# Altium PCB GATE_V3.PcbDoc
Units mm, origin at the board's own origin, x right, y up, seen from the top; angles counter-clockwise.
Board outline 71.37 x 50.42 mm, 2 copper layers (Top Layer, Bottom Layer); 47 components, 44 nets, 244 pads, 54 vias.
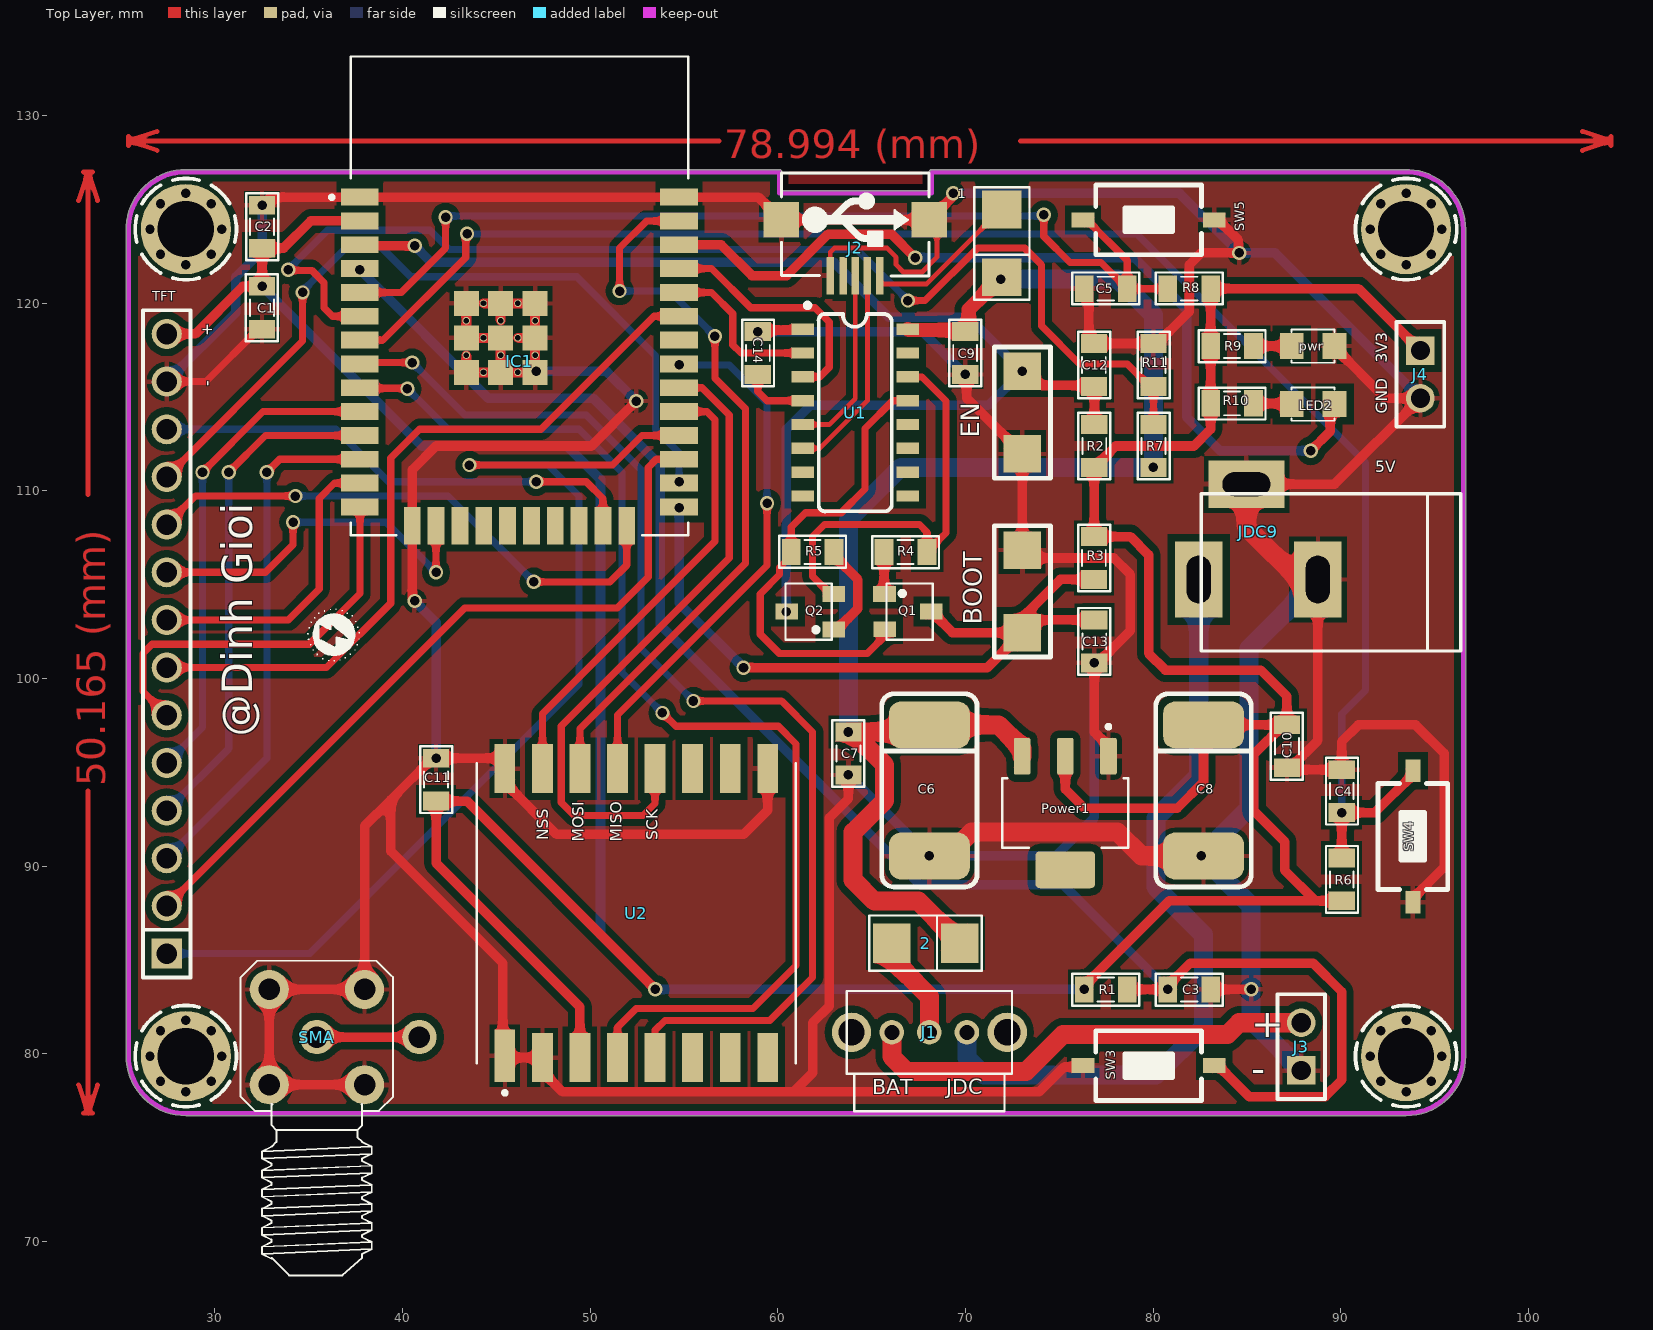
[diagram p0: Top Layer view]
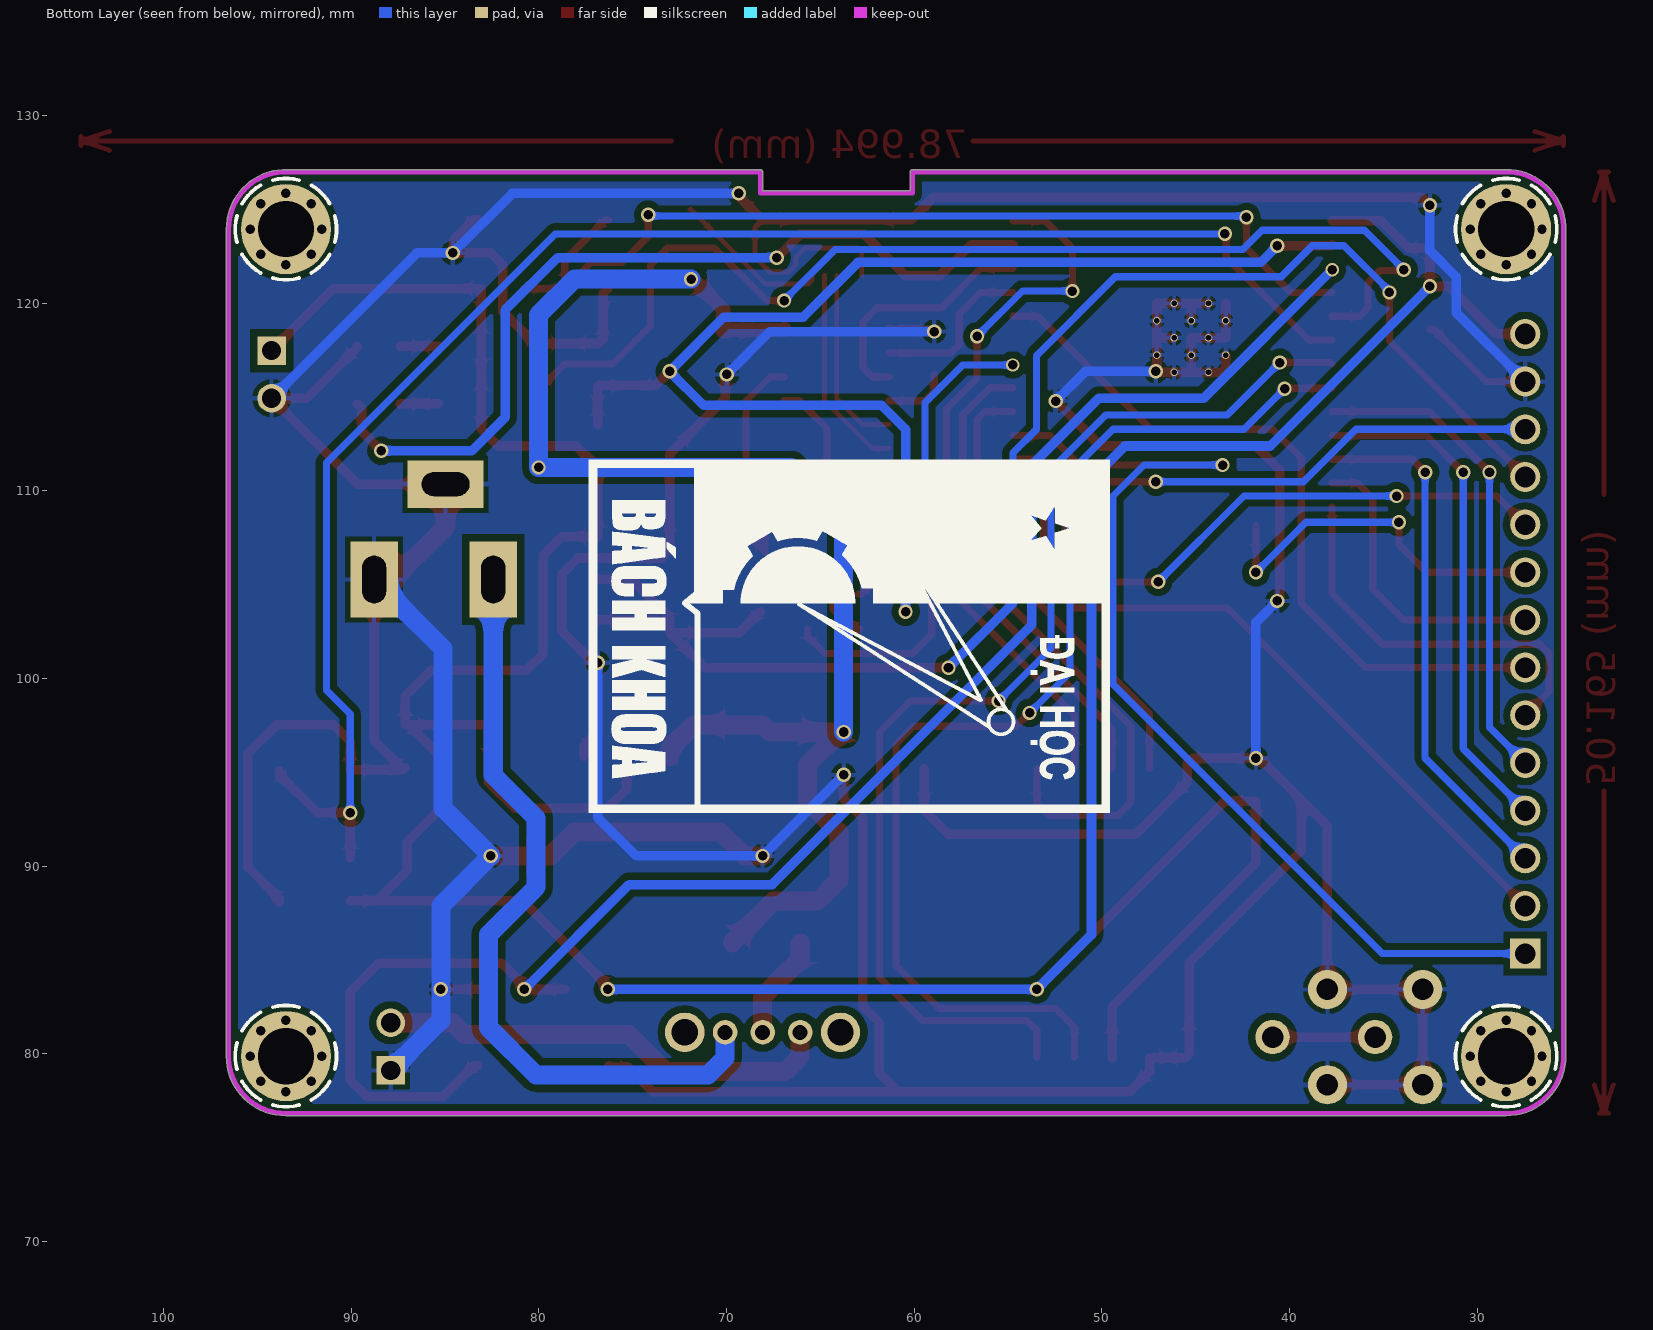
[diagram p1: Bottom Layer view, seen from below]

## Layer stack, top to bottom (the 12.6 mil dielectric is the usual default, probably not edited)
Top Solder: solder mask 0.0102, Solder Resist, Dk 3.5
Top Layer: signal copper 0.0356
Dielectric 1: dielectric 0.32, FR-4, Dk 4.8
Bottom Layer: signal copper 0.0356
Bottom Solder: solder mask 0.0102, Solder Resist, Dk 3.5

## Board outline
28.447,76.708 cw(c28.448,79.883) 25.273,79.883 25.273,123.825 cw(c25.4,123.825) 25.274,123.846 cw(c28.448,123.952) 28.448,127.127 cw(c28.448,127) 28.449,127.127 60.071,127.127 cw(c60.071,127) 60.198,127 60.198,125.984 68.072,125.984 68.072,127 cw(c68.199,127) 68.199,127.127 93.599,127.127 cw(c93.599,127) 93.631,127.123 cw(c93.472,123.952) 96.647,123.952 cw(c96.52,123.952) 96.647,123.951 96.647,80.01 cw(c96.52,80.01) 96.646,79.989 cw(c93.472,79.883) 96.647,79.883 cw(c93.472,79.883) 93.472,76.708 28.448,76.708 cw(c28.448,76.835)

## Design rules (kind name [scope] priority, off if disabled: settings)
Clearance [All] p1: gap=0.254 ignorepadtopadclearanceinfootprint=TRUE except(0.381: Arc-Fill Arc-Poly Arc-Region Track-Fill Track-Poly Track-Region SMDPad-Fill SMDPad-Poly SMDPad-Region THPad-Fill THPad-Poly THPad-Region Via-Fill Via-Poly Via-Region Fill-Fill Fill-Poly Fill-Region Poly-Poly Poly-Region Region-Region)
PolygonConnect [All] p1: connectstyle=Relief reliefconductorwidth=0.254 reliefentries=4 polygonreliefangle="90 Angle" airgapwidth=0.254
RoutingVias [All] p1: holewidth=0.508 width=0.762 viastyle="Through Hole" minholewidth=0.508 minwidth=0.762 maxholewidth=0.711 maxwidth=1.27
SolderMaskExpansion [All] p1: expansion=0.102
Width [All] p1: maxlimit=1.016 minlimit=0.254 preferedwidth=0.508
30 further rules are at their usual default settings.

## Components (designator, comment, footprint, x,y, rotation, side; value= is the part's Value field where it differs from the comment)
1 "S4" DIO-214AC(SMA) 71.882,123.116 r90 top
2 "S4" DIO-214AC(SMA) 67.945,85.852 r180 top
BOOT "SW" "SW 3x2x4" 73.025,104.648 r90 top value="SW chip 2 pin" (schematic designator SW2)
C1 "10uF" CAP_0805 32.512,119.761 r270 top value=33p
C2 "100nF" CAP_0805 32.512,124.079 r90 top value=33p
C3 "100nF" CAP_0805 81.915,83.439 r0 top value=33p
C4 "100nF" CAP_0805 90.043,94.001 r90 top value=33p
C5 "100nF" CAP_0805 77.47,120.777 r180 top value=33p
C6 "22uF/10V" CAP_7343 68.072,94.107 r270 top
C7 "100nF" CAP_0805 63.754,96.012 r270 top value=33p
C8 "22uF/10V" CAP_7343 82.677,94.107 r270 top
C9 "10uF" CAP_0805 69.977,117.348 r90 top value=33p
C10 "100nF" CAP_0805 87.122,96.393 r270 top value=33p
C11 "10uF" CAP_0805 41.783,94.615 r90 top value=33p
C12 "100nF" CAP_0805 76.835,116.713 r90 top value=33p
C13 "100nF" CAP_0805 76.86,101.981 r270 top value=33p
C14 "100nF" CAP_0805 58.928,117.348 r90 top value=33p
EN "SW" "SW 3x2x4" 73.025,114.173 r270 top value="SW chip 2 pin" (schematic designator SW1)
IC1 "ESP32-WROOM-32" MODULE_ESP32-WROOM-32 46.228,120.396 r0 top
J1 "SK12D07VG4" SK12D07VG4 68.07,81.153 r0 top
J2 "USB-5" USB-M1 64.12,121.476 r0 top
J3 "JP2" JP2-C1T 87.884,79.121 r90 top
J4 "JP2" JP2-C1T 94.234,117.475 r270 top
JDC9 "Jac DC" DC-IN 85.598,107.823 r180 top
LED2 "LED" LED-0805-Blue 87.376,114.631 r0 top value="LED 3 ly Single Colour"
Power1 "AMS1117-3V3" SOT230P700X180-4N 75.311,92.837 r270 top
pwr "LED" LED-0805-Blue 87.376,117.717 r0 top value="LED 3 ly Single Colour" (schematic designator LED1)
Q1 "2SC1815" SOT23D 66.929,103.569 r270 top value=C1815
Q2 "2SC1815" SOT23D 61.722,103.569 r90 top value=C1815
R1 "10k" RES_SMD_0805 77.47,83.439 r0 top
R2 "10k" RES-SMD-0805 76.86,112.395 r270 top
R3 "10k" RES-SMD-0805 76.835,106.426 r90 top
R4 "10k" RES-SMD-0805 66.802,106.744 r0 top
R5 "10k" RES-SMD-0805 61.849,106.744 r180 top
R6 "10k" RES_SMD_0805 90.043,89.302 r90 top
R7 "31k" RES-SMD-0805 80.01,112.395 r90 top
R8 "10k" RES_SMD_0805 81.915,120.777 r180 top
R9 "1k" RES-SMD-0805 84.201,117.717 r0 top
R10 "1k" RES-SMD-0805 84.201,114.669 r0 top
R11 "11k" RES-SMD-0805 80.01,116.713 r90 top
SMA "210111003" SMA-RA 35.433,80.899 r0 top
SW3 "SW" SW-SMD 79.756,79.375 r0 top value="SW chip 2 pin"
SW4 "SW" SW-SMD 93.832,91.588 r90 top value="SW chip 2 pin"
SW5 "SW" SW-SMD 79.756,124.444 r180 top value="SW chip 2 pin"
TFT "JP14" JP14-D1T 27.432,85.344 r90 top
U1 "CH340C" SOP-16 64.12,114.173 r270 top
U2 "Ra-02 LoRa" Ra-02 52.451,87.503 r90 top

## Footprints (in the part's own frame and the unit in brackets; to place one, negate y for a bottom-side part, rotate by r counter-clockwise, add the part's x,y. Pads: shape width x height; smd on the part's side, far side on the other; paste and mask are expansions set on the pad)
CAP_0805 [mil]
  rect 39.37x55 smd: 1(-45,0) 2(45,0)
  silkscreen extent -70,-34 70,33, body extent -40,-25 40,25, height 24
CAP_7343 [mm] "Capacitor Tantalum 7343"
  rrect50% 2.5x4.3 smd: 1(-3.429,0) 2(3.556,0)
  silkscreen extent -5.08,-2.54 5.21,2.54, body extent -3.75,-2.14 3.75,2.16, height 2.8
DC-IN [mil] "Jac DC input"
  rect 100x160 hole 50 slot 100 at 90 deg: 1(125,100) 2(-125,100)
  rect 160x100 hole 50 slot 100 at 0 deg: 3(25,-100)
  silkscreen extent -425,-80 120,250, body extent -410,-105 134,269, height 434
DIO-214AC(SMA) [mm] "DO-214AC Diode Smallest Size"
  rect 2x2.1 smd: 1(1.88,-0.051) 2(-1.732,-0.051)
  silkscreen extent -2.92,-1.52 3.07,1.42, body extent -2.5,-1.35 2.7,1.25, height 2.4
JP2-C1T [mm] "2 row, straight, gold plating"
  rect 1.52x1.52 hole 1.02: 1(0,0)
  round 1.52 hole 1.02: 2(2.54,0)
  silkscreen extent -1.52,-1.27 4.06,1.27, body extent -1.52,-1.25 4.06,1.25, height 8.51
JP14-D1T [mm] "14 pins, 1 row, straight, gold plating"
  rect 1.6x1.6 hole 1.1: 1(0,0)
  round 1.6 hole 1.1: 2(2.54,0) 3(5.08,0) 4(7.62,0) 5(10.16,0) 6(12.7,0) 7(15.24,0) 8(17.78,0) 9(20.32,0) 10(22.86,0) 11(25.4,0) 12(27.94,0) 13(30.48,0) 14(33.02,0)
  silkscreen extent -1.27,-1.27 34.29,1.27, body extent -1.27,-1.27 34.29,1.27, height 8.54
LED-0805-Blue [mil]
  rect 50x55 smd: 1(0,0) 2(90,0)
  silkscreen extent 0,-35 90,35, body extent 5,-25 85,25, height 43
MODULE_ESP32-WROOM-32 [mm]
  rect 2x0.9 smd: 1(-8.5,5.26) 2(-8.5,3.99) 3(-8.5,2.72) 4(-8.5,1.45) 5(-8.5,0.18) 6(-8.5,-1.09) 7(-8.5,-2.36) 8(-8.5,-3.63) 9(-8.5,-4.9) 10(-8.5,-6.17) 11(-8.5,-7.44) 12(-8.5,-8.71) 13(-8.5,-9.98) 14(-8.5,-11.25) 25(8.5,-11.25) 26(8.5,-9.98) 27(8.5,-8.71) 28(8.5,-7.44) 29(8.5,-6.17) 30(8.5,-4.9) 31(8.5,-3.63) 32(8.5,-2.36) 33(8.5,-1.09) 34(8.5,0.18) 35(8.5,1.45) 36(8.5,2.72) 37(8.5,3.99) 38(8.5,5.26)
  rect 0.9x2 smd: 15(-5.715,-12.25) 16(-4.445,-12.25) 17(-3.175,-12.25) 18(-1.905,-12.25) 19(-0.635,-12.25) 20(0.635,-12.25) 21(1.905,-12.25) 22(3.175,-12.25) 23(4.445,-12.25) 24(5.715,-12.25)
  rect 1.33x1.33 smd: 39_1(-2.835,-0.405) 39_2(-1,-0.405) 39_3(0.835,-0.405) 39_4(-2.835,-2.24) 39_5(-1,-2.24) 39_6(0.835,-2.24) 39_7(-2.835,-4.075) 39_8(-1,-4.075) 39_9(0.835,-4.075)
  round 0.4 hole 0.3: 39_10(-1.917,-0.405) 39_11(-0.082,-0.405) 39_12(-2.835,-1.322) 39_13(-1,-1.322) 39_14(0.835,-1.322) 39_15(-1.917,-2.24) 39_16(-0.082,-2.24) 39_17(-2.835,-3.157) 39_18(-1,-3.157) 39_19(0.835,-3.157) 39_20(-1.917,-4.075) 39_21(-0.082,-4.075)
  silkscreen extent -10.1,-12.75 9,12.75, body extent -10.54,-12.75 8.98,12.75, height 3.2
Ra-02 [mm]
  rect 2.8x1.1 smd: 1(-7.6,7)
  rect 2.6x1.1 smd: 2(-7.7,5) 3(-7.7,3) 4(-7.7,1) 5(-7.7,-1) 6(-7.7,-3) 7(-7.7,-5) 8(-7.7,-7) 9(7.7,-7) 10(7.7,-5) 11(7.7,-3) 12(7.7,-1) 13(7.7,1) 14(7.7,3) 15(7.7,5) 16(7.7,7)
  silkscreen extent -9.68,-8.5 8,8.5, body extent -8,-8.49 8,8.51, height 3.03
RES-SMD-0805 [mil]
  rect 39.37x55 smd: 1(-45,0) 2(45,0)
  silkscreen extent -70,-34 70,33, body extent -39,-25 39,25, height 31
RES_SMD_0805 [mil]
  rect 39.37x55 smd: 1(-45,0) 2(45,0)
  silkscreen extent -70,-34 70,33, body extent -39,-25 39,25, height 31
SK12D07VG4 [mm]
  round 1.308 hole 0.8: 1(-2,0) 2(2,0) COM(0,0)
  round 2.1 hole 1.4: M1(-4.15,0) M2(4.15,0)
  silkscreen extent -4.4,-4.2 4.4,2.2
SMA-RA [mil]
  round 72 hole 45: 1(0,0)
  round 82 hole 45: 2(-100,-100) 3(100,-100) 4(100,100) 5(-100,100)
  silkscreen extent -160,-500 160,160, body extent -136,-457 139,137, height 394
SOP-16 [mm]
  rect 0.6x1.2 smd: 1(-4.445,-2.8) 2(-3.175,-2.8) 3(-1.905,-2.8) 4(-0.635,-2.8) 5(0.635,-2.8) 6(1.905,-2.8) 7(3.175,-2.8) 8(4.445,-2.8) 9(4.445,2.8) 10(3.175,2.8) 11(1.905,2.8) 12(0.635,2.8) 13(-0.635,2.8) 14(-1.905,2.8) 15(-3.175,2.8) 16(-4.445,2.8)
  silkscreen extent -5.84,-2.67 5.26,1.95, body extent -4.95,-3.47 4.95,3.47, height 1.75
SOT23D [mm] "SOT 23C - 1-3-2 - BCE"
  rect 0.85x1.2 smd: 1(-0.95,-1.25) 2(0.94,-1.245) 3(0,1.25)
  silkscreen extent -1.5,-1.14 1.5,1.32, body extent -1.5,-1.17 1.5,1.33, height 1.06
SOT230P700X180-4N [mm]
  rrect25% 1.97x0.89 smd: 1(-3.025,2.3) 2(-3.025,0) 3(-3.025,-2.3)
  rrect25% 1.97x3.19 smd: 4(3.025,0)
  silkscreen extent -4.7,-3.35 1.85,3.35
"SW 3x2x4" [mm]
  rect 2x2 smd: 1(-2.2,0) 2(2.2,0)
  silkscreen extent -3.5,-1.5 3.5,1.5, body extent -2.45,-1.45 2.45,1.45, height 2
SW-SMD [mm] "Switch SMD type"
  rect 1.2x0.8 smd: 1(-3.5,0) 2(3.5,0)
  silkscreen extent -2.82,-1.85 2.82,1.85, body extent -3.05,-1.85 3.05,1.85, height 2.5
USB-M1 [mm]
  rect 0.4x2 smd: 1(1.3,0) 2(0.65,0) 3(0,0) 4(-0.65,0) 5(-1.321,0)
  rect 1.9x1.9 smd: 5(-3.95,2.968) 5(3.95,2.968)
  silkscreen extent -3.94,-0.03 3.94,5.46, body extent -3.98,0.11 4,5.54, height 2.71

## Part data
1 2: library part "Diode S4", "D醤"
BOOT EN SW3 SW4 SW5: library part SW2, "Switch button 2 pin"
C1 C2 C3 C4 C5 C7 C9 C10 C11 C12 C13 C14: library part CapSMD, "Capacitor"
C6 C8: library part CAP_TAN_SMD, "Polazied Tantalum Capacitor"
IC1: "Bluetooth, WiFi Transceiver Module 2.4GHz ~ 2.5GHz Surface Mount", Package="Module Espressif Systems"
J1: "Switch Slide ON ON SPDT Side Slide 0.3A 30VDC PC Pins Bracket Mount/Through Hole Bulk", Package=None
J2: Manufacturer=FCI, Manufacturer Part Number=10118193-0001LF, Supplier Part Number 1=609-4616-1-ND
J3 J4: "WR-PHD 2.54 mm Angled Socket Header", Manufacturer="Würth Elektronik eiSos GmbH", partNo=613002143121
JDC9: library part DCIN, "Jac DC input"
LED2 pwr: "LED Single colour Green and Red"
Power1: library part LM1117, "800mA Low-Dropout Linear Regulator"
Q1 Q2: library part C1815, "NPN 600mW, ECB"
R1 R4 R5 R6 R8: library part "Resistor - SMD", "Resistor SMD", Manufacturer="Generic Components"
R2 R3 R7 R9 R10 R11: library part "Resistor - SMD", "Resistor", Manufacturer="Generic Components"
SMA: library part "CON Ant", "CONNECTOR ANTEN", Manufacturer="W黵th Elektronik eiSos GmbH"
TFT: "WR-PHD 2.54 mm Angled Socket Header", Manufacturer="Würth Elektronik eiSos GmbH", partNo=613014143121
U1: "USB to serial chip CH340", Package=Package
U2: "LoRa Module Ra-02"

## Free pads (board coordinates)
  round 4.8 hole 3: 16(28.448,79.883) 16(28.448,123.952) 16(93.472,79.883) 16(93.472,123.952)
  round 0.5 hole 0.5: 17(30.353,79.883) 17(30.353,123.952) 17(95.377,79.883) 17(95.377,123.952) 18(29.795,81.23) 18(29.795,125.299) 18(94.819,81.23) 18(94.819,125.299) 19(28.448,81.788) 19(28.448,125.857) 19(93.472,81.788) 19(93.472,125.857) 20(27.101,81.23) 20(27.101,125.299) 20(92.125,81.23) 20(92.125,125.299) 21(26.543,79.883) 21(26.543,123.952) 21(91.567,79.883) 21(91.567,123.952) 22(27.101,78.536) 22(27.101,122.605) 22(92.125,78.536) 22(92.125,122.605) 23(28.448,77.978) 23(28.448,122.047) 23(93.472,77.978) 23(93.472,122.047) 24(29.795,78.536) 24(29.795,122.605) 24(94.819,78.536) 24(94.819,122.605)
  round 1.829 hole 1.143: 25(40.894,80.899)

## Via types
v1: diameter 0.762, hole 0.508, Top Layer to Bottom Layer, 51 vias
v2: diameter 0.711, hole 0.508, Top Layer to Bottom Layer, 3 vias

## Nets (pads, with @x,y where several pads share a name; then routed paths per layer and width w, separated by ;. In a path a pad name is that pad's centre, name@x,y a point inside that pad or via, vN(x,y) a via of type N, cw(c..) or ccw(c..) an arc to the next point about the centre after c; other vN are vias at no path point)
3V3: C1.1 C2.1 C8.1 C10.1 C11.1 IC1.2 J4.1 Power1.2 R1.1 R2.2 R3.2 R6.1 R8.1 R9.1 R10.1 TFT.14 U2.3 | length 214.1
  Top Layer w0.508: TFT.14 28.956,118.364 31.496,120.904 v1(32.512,120.904) C2.1 33.655,122.936 35.105,124.386 IC1.2 ; U2.3 49.451,82.502 41.783,90.17 C11.1 43.434,93.472 v1(53.467,83.439) ; Power1.2 75.311,94.107 76.327,93.091 81.28,93.091 82.677,94.488 C8.1 C10.1@86.923,97.536 ; v1(76.327,83.439) 76.327,83.637 80.849,88.159 R6.1 ; 88.582,88.201 86.995,89.789 86.995,91.313 85.363,92.945 85.363,95.976 C10.1@86.923,97.536 ; J4.1 90.932,120.777 R8.1 R9.1 R10.1 83.058,113.284 82.169,112.395 78.003,112.395 R2.2 76.848,111.239 76.848,107.582 R3.2 78.781,107.569 79.756,106.594 79.756,101.346 80.645,100.457 85.725,100.457 87.122,99.06 C10.1 C10.1@86.924,97.536
  Bottom Layer w0.508: v1(32.512,120.904) 41.021,112.395 48.768,112.395 50.546,110.617 50.546,86.36 v1(53.467,83.439) v1(76.327,83.439)
5V: 1.2 2.2 C6.1 C7.1 C9.2 Power1.3 R7.1 U1.16 | length 79.6
  Top Layer w0.762: U1.16 66.966,118.572 69.896,118.572 C9.2 70.16,118.491 70.168,118.499 70.168,119.668 71.883,121.384 1.2
  Top Layer w1.016: v1(63.754,97.155) 63.937,97.155 65.684,95.407 65.684,93.497 64.008,91.821 64.008,89.266 65.136,88.138 67.492,88.138 69.677,85.953 2.2 ; C7.1@63.762,97.163 67.699,97.163 C6.1 71.751,97.536 73.011,96.276 Power1.3
  Bottom Layer w1.016: v1(63.754,97.155) 63.754,108.458 66.548,111.252 v1(80.01,111.252) 80.01,119.38 78.105,121.285 v1(71.882,121.285)
Adapter: J1.2 JDC9.1 | length 41.3
  Bottom Layer w1.016: J1.2 70.07,79.79 70.993,78.867 80.137,78.867 82.677,81.407 82.677,86.351 80.137,88.891 80.137,92.566 82.423,94.852 JDC9.1
ANTTEN: pad.25 SMA.1 | length 5.5
  Top Layer w0.508: SMA.1 pad.25
CH340_RX: IC1.35 U1.3 | length 13.2
  Top Layer w0.381: IC1.35 56.462,121.846 58.547,119.761 61.976,119.761 62.738,118.999 62.738,116.586 62.23,116.078 U1.3
CH340_TX: IC1.34 U1.2 | length 8.9
  Top Layer w0.381: IC1.34 56.462,120.576 57.594,119.444 57.594,117.78 58.027,117.348 U1.2
CS: IC1.23 TFT.12 | length 26.2
  Top Layer w0.381: v1(47.117,110.49) 49.784,110.49 50.673,109.601 IC1.23
  Bottom Layer w0.381: TFT.12 36.449,113.284 39.243,110.49 v1(47.117,110.49)
D+: J2.3 U1.5 | length 9.9
  Top Layer w0.254: U1.5 62.738,113.538 64.12,114.92 J2.3
D-: J2.2 U1.6 | length 11.2
  Top Layer w0.254: U1.6 62.23,112.268 64.77,114.808 J2.2
D/C: IC1.24 TFT.10 | length 29.5
  Top Layer w0.381: TFT.10 28.956,109.728 v1(34.29,109.728) ; v1(46.99,105.156) 51.054,105.156 51.943,106.045 IC1.24
  Bottom Layer w0.381: v1(34.29,109.728) 42.418,109.728 v1(46.99,105.156)
EN: C12.1 EN.1 IC1.3 Q2.3 R2.1 | length 67.9
  Top Layer w0.508: IC1.3 37.781,123.063 v1(40.64,123.063) ; v1(60.452,103.569) Q2.3 ; v1(73.025,116.373) 73.771,115.627 76.778,115.627 C12.1 76.86,115.545 R2.1
  Bottom Layer w0.508: v1(40.64,123.063) 41.529,122.174 62.992,122.174 65.913,119.253 70.145,119.253 v1(73.025,116.373) 71.206,114.554 61.722,114.554 60.452,113.284 v1(60.452,103.569)
feedback: IC1.6 R7.2 R11.1 | length 62.3
  Top Layer w0.381: v1(33.909,121.793) 33.948,121.754 35.155,121.754 35.814,121.095 35.814,119.761 36.269,119.306 IC1.6 ; v1(66.929,120.142) 67.837,120.142 70.631,122.936 73.152,122.936 74.041,122.047 74.041,118.798 76.073,116.766 78.615,116.766 79.812,115.57 R11.1 R7.2
  Bottom Layer w0.381: v1(33.909,121.793) 36.005,123.888 41.465,123.888 42.481,122.872 64.198,122.872 v1(66.929,120.142)
GND: BOOT.2 C1.2 C2.2 C3.2 C4.2 C5.2 C6.2 C7.2 C8.2 C9.1 C10.2 C11.2 C12.2 C13.2 C14.2 EN.2 IC1.1 IC1.15 IC1.38 IC1.39_1 IC1.39_2 IC1.39_3 IC1.39_4 IC1.39_5 IC1.39_6 IC1.39_7 IC1.39_8 IC1.39_9 IC1.39_10 IC1.39_11 IC1.39_12 IC1.39_13 IC1.39_14 IC1.39_15 IC1.39_16 IC1.39_17 IC1.39_18 IC1.39_19 IC1.39_20 IC1.39_21 J2.5 J3.1 J4.2 JDC9.2 JDC9.3 Power1.1 pwr.2 R11.2 SMA.2 SMA.3 SMA.4 SMA.5 SW3.1 SW4.1 SW5.1 TFT.13 U1.1 U2.1 U2.2 U2.9 U2.16 | length 454.9
  Top Layer w0.254: J2.5@62.799,121.476 62.792,121.484 62.792,122.731 63,122.939 65.813,122.939 66.294,122.458 66.294,122.047 66.675,121.666 67.691,121.666 68.475,122.45 68.475,124.039 J2.5@68.07,124.444
  Top Layer w0.381: TFT.13 29.519,115.824 32.314,118.618 C1.2
  Top Layer w0.508: v1(32.512,125.222) 32.946,125.656 IC1.1 IC1.38 58.958,125.656 60.17,124.444 68.07,124.444 69.293,125.667 69.293,125.808 v1(69.342,125.857) ; SMA.3 SMA.2 SMA.5 SMA.4 37.973,92.146 39.37,93.543 ; v1(40.64,104.14) 40.513,104.267 IC1.15 40.513,111.125 41.783,112.395 50.058,112.395 v1(52.451,114.788) ; IC1.39_17 IC1.39_7 IC1.39_20 IC1.39_8 ; IC1.39_1 IC1.39_12 IC1.39_4 IC1.39_15 IC1.39_5 IC1.39_18 IC1.39_8 ; IC1.39_10 IC1.39_2 ; IC1.39_13 IC1.39_2 ; IC1.39_16 IC1.39_6 ; IC1.39_9 IC1.39_21 IC1.39_8 ; IC1.39_9@47.063,116.373 IC1.39_19 IC1.39_6 ; v1(58.928,118.491) 59.009,118.572 61.274,118.572 U1.1 ; U2.9 59.451,92.979 58.166,91.694 48.21,91.694 45.451,94.453 U2.16 45.451,95.462 45.155,95.758 v1(41.783,95.758) 41.585,95.758 39.37,93.543 ; v1(63.754,94.869) 63.754,93.599 62.738,92.583 62.738,82.55 61.849,81.661 61.849,78.994 60.833,77.978 ; v1(69.977,116.205) 70.055,116.127 70.055,114.943 EN.2 BOOT.2 73.447,106.426 77.892,106.426 78.781,105.537 78.781,102.56 77.059,100.838 v1(76.86,100.838) 76.86,97.153 77.611,96.402 Power1.1 ; SW3.1 76.18,79.299 75.235,79.299 73.914,77.978 60.833,77.978 ; C5.2 76.573,120.531 76.573,118.102 76.819,117.856 C12.2 R11.2 80.208,117.856 81.659,119.306 81.661,119.306 81.915,119.56 81.915,122.047 82.55,122.682 v1(84.582,122.682) 84.533,122.731 84.533,123.366 83.456,124.444 SW5.1 ; C3.2 v1(85.217,83.439) ; JDC9.3 85.725,110.363 89.662,110.363 J4.2 92.38,114.935 89.662,117.653 pwr.2 ; JDC9.2@88.519,105.029 JDC9.2 88.773,96.703 87.32,95.25 C10.2 87.228,95.144 C4.2 90.043,96.645 90.934,97.536 93.98,97.536 95.504,96.012 95.504,89.96 93.832,88.288 SW4.1 ; 39.37,93.543 39.37,90.805 45.339,84.836 45.339,80.015 U2.1 45.551,79.803 U2.2 47.451,79.053 48.526,77.978 60.833,77.978 ; IC1.39_2 IC1.39_11 IC1.39_3 IC1.39_14 IC1.39_6
  Top Layer w1.016: v1(68.072,90.551) 69.035,90.551 70.305,91.821 78.105,91.821 79.375,90.551 C8.2 ; JDC9.3@85.725,110.363 84.963,109.601 84.963,108.077 88.011,105.029 JDC9.2@88.519,105.029
  Bottom Layer w0.508: TFT.13 31.115,119.507 31.115,121.412 32.512,122.809 v1(32.512,125.222) ; v1(40.64,104.14) 41.783,102.997 v1(41.783,95.758) ; v1(47.117,116.373) 50.866,116.373 v1(52.451,114.788) ; v1(58.928,118.491) 67.691,118.491 v1(69.977,116.205) ; v1(63.754,94.869) v1(68.072,90.551) 74.803,90.551 76.86,92.608 v1(76.86,100.838) ; v1(69.342,125.857) 81.407,125.857 v1(84.582,122.682) 86.487,122.682 J4.2
  Bottom Layer w1.016: J3.1 85.218,81.787 v1(85.217,83.439) 85.218,87.883 v1(82.55,90.551) 85.09,93.091 85.09,101.6 JDC9.2
IO_0: BOOT.1 C13.1 IC1.25 Q1.3 R3.1 | length 39.5
  Top Layer w0.508: IC1.25 IC1.25@54.737,109.155 ; v1(58.166,100.584) 71.161,100.584 BOOT.1 ; Q1.3 69.3,102.448 BOOT.1 ; BOOT.1@73.701,103.124 C13.1 ; R3.1 75.057,105.283 73.025,103.251 BOOT.1
  Bottom Layer w0.508: v1(54.737,109.093) 54.737,104.013 v1(58.166,100.584)
IO_35: IC1.36 LED2.2 | length 46.4
  Top Layer w0.508: IC1.36 56.97,123.116 58.61,121.476 60.472,121.476 62.678,123.682 66.056,123.682 v1(67.31,122.428) ; v1(88.392,112.141) 89.421,113.17 89.421,114.39 LED2.2
  Bottom Layer w0.508: v1(67.31,122.428) 78.994,122.428 81.788,119.634 81.788,113.919 83.566,112.141 v1(88.392,112.141)
LED: IC1.33 TFT.7 | length 39.6
  Top Layer w0.381: TFT.7 35.941,100.584 39.37,104.013 39.37,111.76 40.894,113.284 47.371,113.284 53.393,119.306 IC1.33
Lora_DIO0: IC1.8 U2.5 | length 62
  Top Layer w0.381: IC1.8 37.802,116.84 v1(40.513,116.84) ; U2.5 53.451,81.264 53.975,81.788 59.563,81.788 61.849,84.074 61.849,97.155 60.198,98.806 v1(55.499,98.806)
  Bottom Layer w0.381: v1(40.513,116.84) 43.307,114.046 49.784,114.046 52.705,111.125 52.705,101.6 v1(55.499,98.806)
MISO: IC1.31 U2.13 | length 28.3
  Top Layer w0.381: U2.13 51.451,98.06 59.421,106.03 v1(59.421,109.347)
  Bottom Layer w0.381: v2(54.737,116.713) 57.404,116.713 59.421,114.696 v1(59.421,109.347)
MOSI: IC1.37 U2.14 | length 39.5
  Top Layer w0.381: U2.14 49.451,97.33 58.27,106.149 58.27,114.375 56.642,116.003 v1(56.642,118.237) ; v1(51.562,120.65) 51.562,122.939 53.009,124.386 IC1.37
  Bottom Layer w0.381: v1(51.562,120.65) 54.229,120.65 v1(56.642,118.237)
Net1_1: 1.1 J2.1 | length 8.5
  Top Layer w0.254: J2.1 65.42,121.231 65.62,121.031 67.918,121.031 71.883,124.996 1.1
Net2_1: 2.1 J1.COM | length 5.6
  Top Layer w1.016: 2.1 66.065,85.065 68.07,83.06 J1.COM
NetC14_1: C14.1 U1.4 | length 3.5
  Top Layer w0.381: C14.1 58.928,115.301 59.421,114.808 U1.4
NetJ1_1: J1.1 J3.2 | length 24.5
  Top Layer w1.016: J1.1 66.07,79.853 66.87,79.053 73.211,79.053 75.184,81.026 83.947,81.026 84.582,81.661 J3.2
NetLED1_1: pwr.1 R9.2 | length 2
  Top Layer w0.508: R9.2 pwr.1
NetLED2_1: LED2.1 R10.2 | length 2
  Top Layer w0.508: R10.2 85.363,114.65 87.357,114.65 LED2.1
NetQ1_1: Q1.1 R4.1 | length 2.2
  Top Layer w0.508: R4.1 65.659,104.539 Q1.1
NetQ1_2: Q1.2 R5.2 U1.13 | length 25.1
  Top Layer w0.381: Q1.2 65.684,102.26 64.77,101.346 60.071,101.346 59.055,102.362 59.055,104.512 60.086,105.543 60.086,105.925 60.706,106.546 R5.2 60.706,108.077 61.468,108.839 63.373,108.839 64.643,110.109 64.643,113.334 66.117,114.808 U1.13
NetQ2_1: Q2.1 R5.1 | length 5.3
  Top Layer w0.508: Q2.1 63.147,102.619 64.262,103.734 64.262,105.276 62.992,106.546 R5.1
NetQ2_2: Q2.2 R4.2 U1.14 | length 22.2
  Top Layer w0.381: Q2.2 62.792,104.509 61.849,105.451 61.849,107.569 62.484,108.204 67.544,108.204 67.945,107.803 R4.2 68.961,107.76 68.961,114.788 67.671,116.078 U1.14
NSS: IC1.29 U2.15 | length 24.5
  Top Layer w0.381: U2.15 47.451,98.124 56.642,107.315 56.642,113.792 56.208,114.226 IC1.29
Reset_TFT: IC1.26 TFT.11 | length 42.4
  Top Layer w0.381: TFT.11 34.671,117.983 v1(34.671,120.576)
  Bottom Layer w0.381: v1(34.671,120.576) 34.671,120.65 37.084,123.063 38.785,123.063 40.436,121.412 49.276,121.412 53.467,117.221 53.467,113.284 54.737,112.014 v2(54.737,110.49)
Rst_lora: IC1.9 U2.4 | length 61.6
  Top Layer w0.381: IC1.9 37.754,115.469 40.233,115.469 v1(40.259,115.443) ; U2.4 51.451,81.423 52.451,82.423 58.674,82.423 60.96,84.709 60.96,96.52 60.023,97.457 54.562,97.457 v1(53.848,98.171)
  Bottom Layer w0.381: v1(40.259,115.443) 42.418,113.284 49.403,113.284 51.689,110.998 51.689,100.33 v1(53.848,98.171)
SCK: IC1.30 U2.12 | length 35
  Top Layer w0.381: U2.12 53.451,93.35 52.811,92.71 49.149,92.71 48.456,93.403 48.456,97.478 57.404,106.426 57.404,114.046 55.954,115.496 IC1.30
SCK_TFT: IC1.13 TFT.8 | length 16.1
  Top Layer w0.381: TFT.8 33.909,103.124 35.56,104.775 35.56,109.601 36.375,110.416 IC1.13
SDI: IC1.16 TFT.9 | length 19.7
  Top Layer w0.381: TFT.9 32.692,105.664 34.163,107.135 v1(34.163,108.331) ; v1(41.783,105.664) IC1.16
  Bottom Layer w0.381: v1(34.163,108.331) 39.116,108.331 v1(41.783,105.664)
SDO: IC1.14 TFT.6 | length 21.3
  Top Layer w0.381: TFT.6 26.162,99.314 26.162,101.346 26.645,101.829 35.027,101.829 37.728,104.53 IC1.14
SW1: C3.1 IC1.4 R1.2 SW3.2 | length 89.2
  Top Layer w0.508: R1.2 v1(80.772,83.439) 80.772,83.637 81.97,84.836 88.519,84.836 90.043,83.312 90.043,78.613 89.154,77.724 85.107,77.724 83.456,79.375 SW3.2
  Bottom Layer w0.508: v2(37.719,121.793) 44.577,114.935 50.165,114.935 53.721,111.379 53.721,102.87 67.564,89.027 75.184,89.027 v1(80.772,83.439)
SW2: C4.1 IC1.7 R6.2 SW4.2 | length 88.1
  Top Layer w0.381: IC1.7 38.961,118.036 43.361,122.436 43.361,123.625 v1(43.434,123.698)
  Top Layer w0.508: R6.2 v1(90.043,92.858) 91.802,92.858 93.832,94.888 SW4.2
  Bottom Layer w0.381: v1(43.434,123.698) 79.121,123.698 91.313,111.506 91.313,99.376 90.043,98.106 v1(90.043,92.858)
SW3: C5.1 IC1.5 R8.2 SW5.2 | length 52.8
  Top Layer w0.381: IC1.5 39.931,120.576 42.291,122.936 v1(42.291,124.587) ; v1(74.168,124.714) 74.168,123.571 75.565,122.174 77.216,122.174 C5.1 ; SW5.2 76.456,124.444 78.613,122.287 C5.1 ; R8.2 C5.1
  Bottom Layer w0.381: v1(42.291,124.587) 42.355,124.65 74.105,124.65 v1(74.168,124.714)
T_CLK: IC1.10 TFT.5 | length 26
  Top Layer w0.381: v1(29.337,110.998) 32.565,114.226 IC1.10
  Bottom Layer w0.381: TFT.5 29.337,97.409 v1(29.337,110.998)
T_CS: IC1.11 TFT.4 | length 27.2
  Top Layer w0.381: v1(30.734,110.998) 32.692,112.956 IC1.11
  Bottom Layer w0.381: TFT.4 30.734,96.266 v1(30.734,110.998)
T_DIN: IC1.12 TFT.3 | length 28
  Top Layer w0.381: v1(32.766,110.998) 33.454,111.686 IC1.12
  Bottom Layer w0.381: TFT.3 32.766,95.758 v1(32.766,110.998)
T_IRQ: IC1.28 TFT.1 | length 56.3
  Top Layer w0.381: v1(43.561,111.379) 51.181,111.379 52.758,112.956 IC1.28
  Bottom Layer w0.381: TFT.1 35.052,85.344 49.403,99.695 49.403,109.728 47.752,111.379 v1(43.561,111.379)
T_OUT: IC1.27 TFT.2 | length 40.6
  Top Layer w0.381: TFT.2 43.307,103.759 51.435,103.759 53.086,105.41 53.086,111.252 53.52,111.686 IC1.27
pads on no net: IC1.17 IC1.18 IC1.19 IC1.20 IC1.21 IC1.22 IC1.32 J1.M1 J1.M2 J2.4 Power1.4 U1.7 U1.8 U1.9 U1.10 U1.11 U1.12 U1.15 U2.6 U2.7 U2.8 U2.10 U2.11
copper on no net: | length 112.2
  Top Layer w0.254: 22.733,78.359 23.241,76.835 ; 22.733,125.476 23.241,127 ; 22.987,76.835 23.495,76.835 ; 22.987,127 23.495,127 ; 23.241,94.021 23.241,76.835 ; 23.241,109.814 23.241,127 ; 23.749,78.359 23.241,76.835 ; 23.749,125.476 23.241,127 ; 25.4,128.397 25.4,128.905 ; 26.924,128.143 25.4,128.651 ; 26.924,129.159 25.4,128.651 ; 56.873,128.651 25.4,128.651 ; 72.921,128.651 104.394,128.651 ; 102.87,128.143 104.394,128.651 ; 102.87,129.159 104.394,128.651 ; 104.394,128.397 104.394,128.905

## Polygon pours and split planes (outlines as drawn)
GND on Bottom Layer "Bottom Layer-GND" (solid, pour order 2): 25.527,125.349 26.67,126.492 27.432,126.492 27.94,127 60.071,127 60.071,125.857 67.945,125.857 68.199,126.111 68.199,127 93.599,127 93.726,126.873 94.615,126.873 94.996,126.492 95.123,126.492 95.631,125.984 95.631,125.934 96.393,125.172 96.393,124.714 96.52,124.587 96.52,79.121 96.266,78.867 96.266,78.105 96.012,77.851 96.012,77.724 95.631,77.724 95.25,77.343 94.819,77.343 94.819,77.293 94.361,76.835 92.964,76.835 92.961,76.838 27.556,76.838 27.305,77.089 27.051,77.089 26.416,77.724 26.289,77.724 26.035,77.978 26.035,78.282 25.654,78.663 25.654,79.121 25.4,79.375 25.4,124.587 25.527,124.714
GND on Top Layer "Top Layer-GND" (solid, pour order 4): 25.403,124.206 25.403,124.587 25.654,124.838 25.654,125.402 26.035,125.783 26.035,125.984 26.289,125.984 26.543,126.238 26.543,126.365 26.797,126.365 27.178,126.746 27.559,126.746 27.813,127 93.599,127 93.726,126.873 94.234,126.873 94.361,126.746 94.742,126.746 94.869,126.619 95.123,126.619 95.631,126.111 95.631,125.984 95.758,125.984 96.012,125.73 96.012,125.603 96.266,125.349 96.266,125.123 96.393,124.996 96.393,124.513 96.52,124.386 96.52,79.505 96.517,79.502 96.52,79.499 96.52,78.87 96.393,78.743 96.393,78.74 96.266,78.74 96.139,78.613 96.139,78.359 95.504,77.724 95.504,77.597 95.377,77.47 95.123,77.47 94.869,77.216 94.615,77.216 94.234,76.835 28.448,76.835 28.445,76.838 27.683,76.838 27.432,77.089 26.924,77.089 26.416,77.597 26.416,77.724 25.654,78.486 25.654,78.867 25.273,79.248 25.273,79.883 25.4,80.01 25.4,124.587 25.654,124.841

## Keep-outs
Keep-Out Layer:
  lines w0.254: 25.4,123.825 25.4,79.883 ccw(c28.448,79.883) 28.575,76.838 ; 25.403,123.825 cw(c28.448,123.952) 28.448,127 60.071,127 60.071,125.857 68.199,125.857 68.199,127 93.599,127 ; 28.448,76.835 93.472,76.835 ccw(c93.472,79.883) 96.517,80.01 ; 93.345,126.997 cw(c93.472,123.952) 96.52,123.952 96.52,80.01

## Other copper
Top Layer:
  text "78.994 (mm)" at 57.127,127.737 h1.52
  text "50.165 (mm)" at 24.155,94.275 h1.52 r90

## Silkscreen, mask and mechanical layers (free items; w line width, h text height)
Top Overlay:
  drawing of 236 lines, arcs and shapes, not listed
  text "+" at 29.845,118.237 h0.6 r90
  text "3V3" at 92.456,116.84 h0.6 r90
  text "-" at 29.845,115.57 h0.6 r90
  text "GND" at 92.456,114.122 h0.6 r90
  text "5V" at 91.821,110.998 h0.6
  text "@Dinh Gioi" at 32.512,96.901 h2.8 r90
  text "NSS" at 47.752,91.389 h0.6 r90
  text "SCK" at 53.594,91.389 h0.6 r90
  text "MOSI" at 49.657,91.313 h0.6 r90
  text "MISO" at 51.689,91.313 h0.6 r90
  text "+" at 85.217,80.899 h1.52
  text "-" at 85.217,78.486 h1.52
  text "BAT" at 65.024,77.851 h0.8
  text "JDC" at 68.961,77.851 h0.8
Bottom Overlay:
  drawing of 11675 lines, arcs and shapes, not listed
